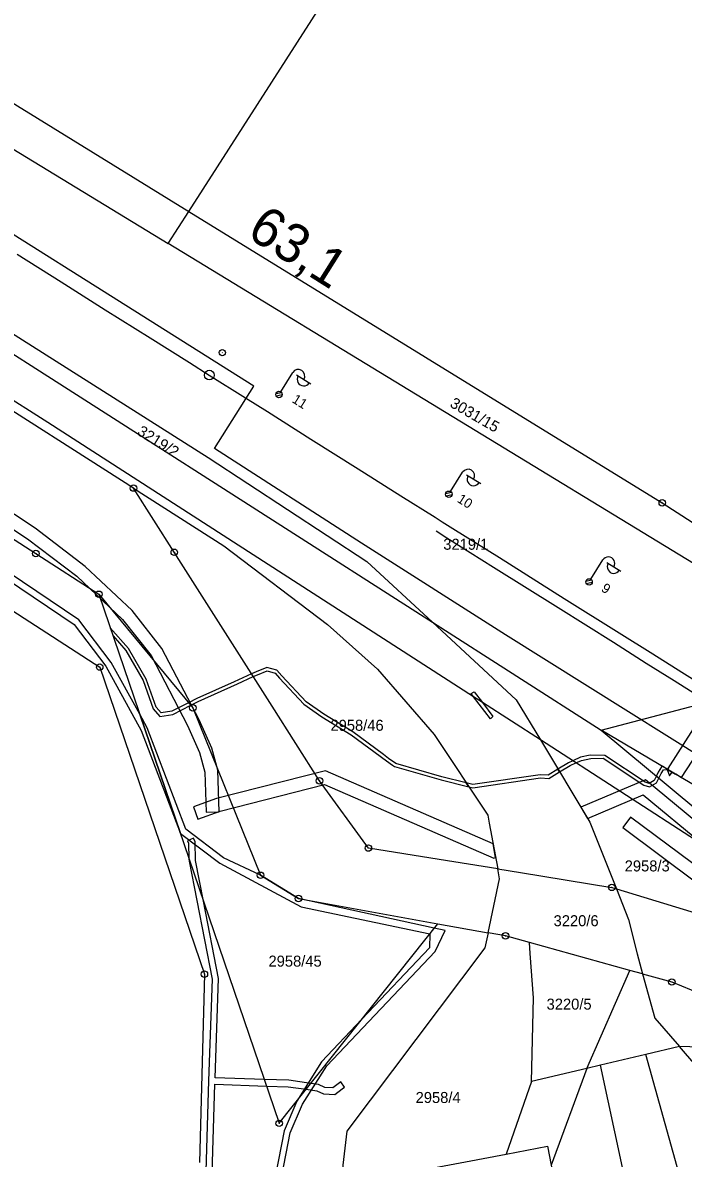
# Model space of a CAD drawing. Extents: x -621168 to -620292, y -1122748 to -1122069.
# Drawn here: x -620574.6 to -620472.5, y -1122640.4 to -1122465.1 of the extents above; entities that cross this region are included whole.
import ezdxf

# ---------------------------------------------------------------- set-up
doc = ezdxf.new("R2010")
doc.units = 0
for name, color, linetype in [('HranDP', 7, 'Continuous'), ('Hranice parcel', 7, 'Continuous'), ('Parcelní čísla', 7, 'Continuous'), ('Vnitřní kresba', 7, 'Continuous'), ('Vrstva 1', 7, 'Continuous'), ('Vrstva 14', 7, 'Continuous'), ('Vrstva 25', 7, 'Continuous'), ('Vrstva 7', 7, 'Continuous'), ('Věcná břemena k části', 7, 'Continuous'), ('Značky bodu BP', 7, 'Continuous')]:
    doc.layers.add(name, color=color, linetype=linetype)

msp = doc.modelspace()

# ---------------------------------------------------------------- linework, layer by layer
at = {"layer": 'HranDP'}
for p, q in [((-620445.8, -1122563.95), (-620552.09, -1122499.2)), ((-620511.29, -1122557.64), (-620485.21, -1122574.33))]:
    msp.add_line(p, q, dxfattribs=at)
for points in [[(-620847.72, -1122320.67), (-620838.83, -1122326.12), (-620768.63, -1122369.09), (-620748.53, -1122378.52), (-620702.13, -1122406.7), (-620691.02, -1122413.66), (-620638.48, -1122446.57), (-620552.09, -1122499.2)], [(-620821.12, -1122358.76), (-620741.46, -1122408.09), (-620679.51, -1122447.56), (-620545.92, -1122532.26), (-620521.41, -1122548.27), (-620511.29, -1122557.64)], [(-620378.58, -1122639.67), (-620411.71, -1122617.81), (-620485.21, -1122574.33)]]:
    msp.add_lwpolyline(points, dxfattribs=at)
at = {"layer": 'Hranice parcel'}
for p, q in [((-620548.9, -1122494.24), (-620477.85, -1122383.56)), ((-620688.16, -1122408.5), (-620548.9, -1122494.24)), ((-620552.09, -1122499.2), (-620548.9, -1122494.24)), ((-620548.9, -1122494.24), (-620475.79, -1122539.24)), ((-620445.8, -1122563.95), (-620552.09, -1122499.2)), ((-620511.29, -1122557.64), (-620485.21, -1122574.33)), ((-620482.88, -1122598.82), (-620481, -1122603.54)), ((-620510.44, -1122604.21), (-620502.69, -1122605.61)), ((-620546.5, -1122612), (-620547.23, -1122641.1)), ((-620478.83, -1122611.96), (-620476.96, -1122618.82)), ((-620476.96, -1122618.82), (-620473.14, -1122623.15)), ((-620473.14, -1122623.15), (-620478.32, -1122624.38)), ((-620478.32, -1122624.38), (-620485.31, -1122626.04))]:
    msp.add_line(p, q, dxfattribs=at)
for points in [[(-620847.72, -1122320.67), (-620838.83, -1122326.12), (-620768.63, -1122369.09), (-620748.53, -1122378.52), (-620702.13, -1122406.7), (-620691.02, -1122413.66), (-620638.48, -1122446.57), (-620552.09, -1122499.2)], [(-620821.12, -1122358.76), (-620741.46, -1122408.09), (-620679.51, -1122447.56), (-620545.92, -1122532.26), (-620521.41, -1122548.27), (-620511.29, -1122557.64)], [(-620821.12, -1122358.76), (-620807.67, -1122367.84), (-620645.72, -1122471.03), (-620587.17, -1122509.18), (-620511.29, -1122557.64)], [(-620557.45, -1122536.96), (-620684.91, -1122455.63), (-620825.92, -1122365.89)], [(-620501.2, -1122595.75), (-620510.22, -1122594.3), (-620521.17, -1122592.53), (-620528.72, -1122582.15), (-620536.04, -1122570.64), (-620547.19, -1122553.1), (-620551.15, -1122546.87), (-620557.45, -1122536.96)], [(-620557.45, -1122536.96), (-620543.5, -1122545.86), (-620527.5, -1122558.02), (-620519.77, -1122564.93), (-620511.02, -1122574.99), (-620502.74, -1122587.44), (-620502.51, -1122588.68), (-620501.2, -1122595.75)], [(-620475.79, -1122539.24), (-620450.17, -1122555.76), (-620441.78, -1122561.82)], [(-620576.58, -1122544.45), (-620572.54, -1122547.06), (-620562.8, -1122553.35)], [(-620581.67, -1122552.32), (-620562.67, -1122564.59), (-620546.5, -1122612)], [(-620562.8, -1122553.35), (-620548.28, -1122570.88), (-620537.83, -1122596.73), (-620531.96, -1122600.32), (-620510.44, -1122604.21)], [(-620562.8, -1122553.35), (-620534.95, -1122635.03), (-620510.44, -1122604.21)], [(-620511.29, -1122557.64), (-620498.35, -1122569.65), (-620494.61, -1122575.85)], [(-620485.21, -1122574.33), (-620466.94, -1122589.51), (-620387.14, -1122654.39)], [(-620378.58, -1122639.67), (-620411.71, -1122617.81), (-620485.21, -1122574.33)], [(-620494.61, -1122575.85), (-620486.95, -1122588.56), (-620482.88, -1122598.82)], [(-620450.13, -1122608.86), (-620469.8, -1122591.86), (-620494.61, -1122575.85)], [(-620502.69, -1122605.61), (-620500.92, -1122597.26), (-620501.2, -1122595.75)], [(-620501.2, -1122595.75), (-620497.68, -1122596.32), (-620483.58, -1122598.6), (-620482.88, -1122598.82)], [(-620482.88, -1122598.82), (-620472.56, -1122601.98), (-620450.13, -1122608.86)], [(-620481, -1122603.54), (-620479.67, -1122608.86), (-620478.83, -1122611.96)], [(-620502.69, -1122605.61), (-620503.19, -1122607.95), (-620524.52, -1122636.25), (-620525.13, -1122641.47), (-620525.33, -1122649.53), (-620522.29, -1122666.99)], [(-620496.31, -1122607.11), (-620500, -1122606.09), (-620502.69, -1122605.61)], [(-620485.31, -1122626.04), (-620487.46, -1122626.56), (-620495.96, -1122628.58), (-620495.65, -1122615.65), (-620496.18, -1122608.79), (-620496.31, -1122607.11)], [(-620478.83, -1122611.96), (-620480.79, -1122611.41), (-620496.31, -1122607.11)], [(-620478.83, -1122611.96), (-620474.31, -1122613.21), (-620471.33, -1122614.44), (-620452.73, -1122622.13)], [(-620450.04, -1122631.61), (-620461.53, -1122623.57), (-620463.51, -1122623.5), (-620473.14, -1122623.15)], [(-620410.99, -1122695.4), (-620434.88, -1122667.63), (-620473.14, -1122623.15)], [(-620438.61, -1122680.28), (-620439.78, -1122679.56), (-620451.85, -1122677.25), (-620463.28, -1122678.3), (-620478.32, -1122624.38)], [(-620486.3, -1122676.15), (-620484.21, -1122674.6), (-620475.28, -1122672.75), (-620485.31, -1122626.04)], [(-620522.29, -1122666.99), (-620515.05, -1122665.61), (-620511.55, -1122664.94), (-620512.68, -1122659.03), (-620515.78, -1122642.8), (-620506.17, -1122640.97), (-620499.9, -1122639.77), (-620493.5, -1122638.55), (-620492.94, -1122641.47), (-620486.3, -1122676.15)]]:
    msp.add_lwpolyline(points, dxfattribs=at)
at = {"layer": 'Vnitřní kresba'}
for p, q in [((-620570.69, -1122526.84), (-620613.12, -1122500)), ((-620504.94, -1122569.2), (-620570.69, -1122526.84)), ((-620485.21, -1122574.33), (-620445.8, -1122563.95)), ((-620505.32, -1122568.68), (-620504.84, -1122568.4)), ((-620504.94, -1122569.2), (-620505.32, -1122568.68)), ((-620503.56, -1122570.07), (-620504.94, -1122569.2)), ((-620502.33, -1122572.56), (-620504.94, -1122569.2)), ((-620504.84, -1122568.4), (-620503.56, -1122570.07)), ((-620494.61, -1122575.85), (-620503.56, -1122570.07)), ((-620503.56, -1122570.07), (-620501.96, -1122572.22)), ((-620501.96, -1122572.22), (-620502.33, -1122572.56)), ((-620487.46, -1122626.56), (-620480.79, -1122611.41)), ((-620487.46, -1122626.56), (-620492.94, -1122641.47)), ((-620495.96, -1122628.58), (-620499.9, -1122639.77))]:
    msp.add_line(p, q, dxfattribs=at)
at = {"layer": 'Vrstva 1'}
msp.add_line((-620544.95, -1122530.86), (-620538.89, -1122521.21), dxfattribs=at)
for points in [[(-620538.89, -1122521.21), (-620599.21, -1122483.22), (-620683.52, -1122429.44), (-620747.38, -1122389.13), (-620756.33, -1122383.52)], [(-620575.44, -1122500.82), (-620568.6, -1122505.12), (-620561.8, -1122509.42), (-620554.88, -1122513.77), (-620548.82, -1122517.58), (-620545.74, -1122519.52), (-620540.16, -1122523.03), (-620536.76, -1122525.16), (-620530.04, -1122529.4), (-620522.74, -1122534), (-620516.18, -1122538.13), (-620510.88, -1122541.46), (-620509.77, -1122542.15), (-620508.12, -1122543.19), (-620500.94, -1122547.69), (-620490.94, -1122553.98), (-620482.44, -1122559.31), (-620477.26, -1122562.56), (-620472.76, -1122565.38), (-620464.48, -1122570.59)], [(-620456.11, -1122587.12), (-620500.01, -1122559.59), (-620522.22, -1122545.45), (-620544.95, -1122530.86)]]:
    msp.add_lwpolyline(points, dxfattribs=at)
at = {"layer": 'Vrstva 14'}
msp.add_lwpolyline([(-620510.69, -1122543.55), (-620509.04, -1122544.63), (-620501.84, -1122549.15), (-620491.85, -1122555.41), (-620483.32, -1122560.77), (-620478.25, -1122563.97), (-620473.97, -1122566.66), (-620465.4, -1122572.05), (-620457.72, -1122576.88), (-620450.01, -1122581.72), (-620442.29, -1122586.56), (-620434.63, -1122591.38), (-620426.95, -1122596.21), (-620419.24, -1122601.09), (-620411.54, -1122605.96), (-620403.8, -1122610.84), (-620395.25, -1122616.25), (-620387.51, -1122621.12), (-620379.87, -1122625.94), (-620375.57, -1122628.64), (-620373.08, -1122630.21)], dxfattribs=at)
at = {"layer": 'Vrstva 25'}
for p, q in [((-620534.71, -1122522.08), (-620532.84, -1122519.12)), ((-620532.25, -1122519.49), (-620530.05, -1122520.88)), ((-620535.46, -1122522.37), (-620534.6, -1122522.18)), ((-620535.41, -1122522.74), (-620534.48, -1122522.53)), ((-620508.48, -1122537.48), (-620506.62, -1122534.52)), ((-620506.02, -1122534.89), (-620503.82, -1122536.27)), ((-620509.23, -1122537.78), (-620508.37, -1122537.58)), ((-620509.18, -1122538.15), (-620508.25, -1122537.94)), ((-620486.83, -1122551.02), (-620484.96, -1122548.06)), ((-620484.37, -1122548.43), (-620482.17, -1122549.81)), ((-620487.57, -1122551.32), (-620486.72, -1122551.12)), ((-620487.53, -1122551.69), (-620486.59, -1122551.48))]:
    msp.add_line(p, q, dxfattribs=at)
for centre in [(-620534.98, -1122522.5), (-620508.74, -1122537.91), (-620487.09, -1122551.45)]:
    msp.add_circle(centre, 0.5, dxfattribs=at)
for centre, start, end in [((-620532, -1122519.65), 327.7645, 147.7645), ((-620531.16, -1122520.19), 147.0619, 328.467), ((-620505.77, -1122535.05), 327.8645, 147.8645), ((-620504.93, -1122535.59), 147.162, 328.5671), ((-620484.12, -1122548.59), 327.8803, 147.8803), ((-620483.28, -1122549.13), 147.1777, 328.5829)]:
    msp.add_arc(centre, 1, start, end, dxfattribs=at)
at = {"layer": 'Vrstva 7'}
msp.add_line((-620543.78, -1122516.02), (-620543.69, -1122516.08), dxfattribs=at)
for centre, radius in [((-620543.73, -1122516.05), 0.5), ((-620545.74, -1122519.52), 0.75)]:
    msp.add_circle(centre, radius, dxfattribs=at)
at = {"layer": 'Věcná břemena k části'}
for points in [[(-620662.49, -1122492.8), (-620663.99, -1122495.13), (-620660.86, -1122494.48), (-620566.61, -1122558.04), (-620561.72, -1122564.46), (-620556.24, -1122574.37), (-620550.21, -1122590.27), (-620556.49, -1122571.86), (-620560.88, -1122563.9), (-620565.91, -1122557.3), (-620661.78, -1122492.65)], [(-620456.96, -1122557.15), (-620459.28, -1122555.74), (-620474.94, -1122580.24), (-620474.78, -1122580.35), (-620474.85, -1122580.46), (-620473.73, -1122581.12), (-620473.69, -1122581.06), (-620472.83, -1122581.63), (-620471.16, -1122579.11), (-620461.86, -1122564.94)], [(-620551.52, -1122571.42), (-620553.2, -1122571.67), (-620553.96, -1122570.77), (-620555.49, -1122566.47), (-620558.24, -1122561.71), (-620561.03, -1122558.53), (-620560.61, -1122559.77), (-620558.64, -1122562.01), (-620555.95, -1122566.69), (-620554.4, -1122571.03), (-620553.4, -1122572.21), (-620551.36, -1122571.9), (-620548.6, -1122570.49), (-620547.46, -1122569.91), (-620541.41, -1122567.17), (-620538.95, -1122566.06), (-620538.32, -1122565.78), (-620536.81, -1122565.17), (-620535.58, -1122565.51), (-620534.89, -1122566.28), (-620531.14, -1122570.32), (-620528.34, -1122572.29), (-620523.83, -1122575.03), (-620518.35, -1122579.09), (-620517.46, -1122579.72), (-620517.13, -1122579.95), (-620509.95, -1122582.01), (-620505.65, -1122583.07), (-620506.06, -1122582.46), (-620509.83, -1122581.53), (-620516.91, -1122579.49), (-620518.05, -1122578.69), (-620518.83, -1122578.11), (-620523.55, -1122574.61), (-620528.06, -1122571.87), (-620530.8, -1122569.94), (-620534.53, -1122565.94), (-620535.3, -1122565.07), (-620536.85, -1122564.65), (-620538.52, -1122565.32), (-620539.22, -1122565.64), (-620541.91, -1122566.85), (-620547.68, -1122569.45), (-620548.93, -1122570.09)], [(-620476.66, -1122582.45), (-620476.31, -1122581.73), (-620476.7, -1122581.4), (-620477.04, -1122582.09), (-620477.83, -1122582.55), (-620478.41, -1122582.37), (-620484.64, -1122578.24), (-620486.9, -1122578.2), (-620488.41, -1122578.51), (-620489.62, -1122579.07), (-620490.27, -1122579.37), (-620491.9, -1122580.35), (-620491.64, -1122580.78), (-620490.03, -1122579.81), (-620489.12, -1122579.39), (-620488.25, -1122578.99), (-620486.8, -1122578.7), (-620484.92, -1122578.66), (-620478.63, -1122582.83), (-620477.77, -1122583.09)], [(-620476.7, -1122581.4), (-620476.31, -1122581.73), (-620475.97, -1122581.04), (-620475.6, -1122580.46), (-620475.01, -1122580.41), (-620474.65, -1122581.39), (-620474.27, -1122580.8), (-620474.85, -1122580.46), (-620475.69, -1122579.96), (-620475.88, -1122579.98), (-620476.41, -1122580.8)], [(-620547.49, -1122588.06), (-620544.04, -1122586.82), (-620527.96, -1122582.73), (-620501.79, -1122594.1), (-620501.53, -1122593.99), (-620501.92, -1122591.86), (-620527.8, -1122580.63), (-620544.62, -1122584.9), (-620548.17, -1122586.18)], [(-620505.65, -1122583.07), (-620505.06, -1122583.21), (-620494.61, -1122581.71), (-620493.3, -1122581.78), (-620491.64, -1122580.78), (-620491.9, -1122580.35), (-620493.42, -1122581.28), (-620494.63, -1122581.21), (-620505.04, -1122582.71), (-620506.06, -1122582.46)], [(-620481.88, -1122589.35), (-620470.44, -1122597.88), (-620469.24, -1122596.28), (-620480.68, -1122587.75)]]:
    msp.add_lwpolyline(points, close=True, dxfattribs=at)
for points in [[(-620586.86, -1122536.18), (-620573.8, -1122544.78), (-620566.2, -1122550.57), (-620559.13, -1122557.24), (-620554.74, -1122562.8), (-620549.11, -1122573.63), (-620547.24, -1122577.78), (-620546.44, -1122580.81), (-620546.21, -1122587), (-620544.21, -1122586.92), (-620544.44, -1122580.51), (-620545.34, -1122577.1), (-620547.31, -1122572.75), (-620553.06, -1122561.7), (-620557.65, -1122555.88), (-620564.9, -1122549.05), (-620572.64, -1122543.14), (-620585.76, -1122534.5)], [(-620534.53, -1122643.11), (-620533.24, -1122636.48), (-620531.35, -1122632.09), (-620527.61, -1122626.14), (-620510.87, -1122608.51), (-620509.33, -1122605.27), (-620511, -1122604.91), (-620531.96, -1122600.32), (-620537.83, -1122596.73), (-620543.57, -1122594.05), (-620549.38, -1122589.64), (-620555.33, -1122573.96), (-620556.49, -1122571.86), (-620550.21, -1122590.27), (-620544.11, -1122594.89), (-620531.56, -1122601.62), (-620511.69, -1122605.79), (-620511.71, -1122607.93), (-620522.17, -1122618.96), (-620528.4, -1122625.53), (-620532.24, -1122631.63), (-620534.2, -1122636.18), (-620535.53, -1122643.03)], [(-620394.32, -1122666.74), (-620417.42, -1122647.16), (-620431.52, -1122639.64), (-620457.44, -1122620.38), (-620448.45, -1122606.75), (-620478.4, -1122581.98), (-620488.36, -1122586.21), (-620487.32, -1122587.95), (-620478.74, -1122584.3), (-620451.11, -1122607.15), (-620460.16, -1122620.86), (-620432.6, -1122641.34), (-620418.54, -1122648.82), (-620395.34, -1122668.49)], [(-620545.91, -1122663.42), (-620544.9, -1122629), (-620536.91, -1122629.27), (-620533.56, -1122629.38), (-620530.78, -1122629.78), (-620529.16, -1122630.02), (-620528.1, -1122630.5), (-620526.34, -1122630.56), (-620525.24, -1122629.73), (-620524.84, -1122629.43), (-620525.44, -1122628.63), (-620525.84, -1122628.93), (-620526.66, -1122629.54), (-620527.88, -1122629.5), (-620528.88, -1122629.06), (-620530.06, -1122628.89), (-620533.48, -1122628.38), (-620537.26, -1122628.25), (-620544.86, -1122628), (-620544.3, -1122612.69), (-620546.64, -1122600.75), (-620547.87, -1122594.46), (-620547.94, -1122591.57), (-620548.19, -1122591), (-620549.11, -1122591.4), (-620548.94, -1122591.79), (-620548.88, -1122594.18), (-620548.87, -1122594.56), (-620545.3, -1122612.77), (-620545.88, -1122628.46), (-620546.91, -1122663.38)]]:
    msp.add_lwpolyline(points, dxfattribs=at)
at = {"layer": 'Značky bodu BP'}
for centre, radius in [((-620557.45, -1122536.96), 0.5), ((-620557.45, -1122536.96), 0.0303), ((-620475.79, -1122539.24), 0.5), ((-620475.79, -1122539.24), 0.0303), ((-620572.54, -1122547.06), 0.5), ((-620551.15, -1122546.87), 0.5), ((-620572.54, -1122547.06), 0.0303), ((-620551.15, -1122546.87), 0.0303), ((-620562.8, -1122553.35), 0.5), ((-620562.8, -1122553.35), 0.0303), ((-620562.67, -1122564.59), 0.5), ((-620562.67, -1122564.59), 0.0303), ((-620548.28, -1122570.88), 0.5), ((-620548.28, -1122570.88), 0.0303), ((-620528.72, -1122582.15), 0.5), ((-620528.72, -1122582.15), 0.0303), ((-620521.17, -1122592.53), 0.5), ((-620521.17, -1122592.53), 0.0303), ((-620537.83, -1122596.73), 0.5), ((-620537.83, -1122596.73), 0.0303), ((-620483.58, -1122598.6), 0.5), ((-620483.58, -1122598.6), 0.0303), ((-620531.96, -1122600.32), 0.5), ((-620531.96, -1122600.32), 0.0303), ((-620500, -1122606.09), 0.5), ((-620500, -1122606.09), 0.0303), ((-620546.5, -1122612), 0.5), ((-620546.5, -1122612), 0.0303), ((-620474.31, -1122613.21), 0.5), ((-620474.31, -1122613.21), 0.0303), ((-620534.95, -1122635.03), 0.5), ((-620534.95, -1122635.03), 0.0303)]:
    msp.add_circle(centre, radius, dxfattribs=at)

# ---------------------------------------------------------------- texts
at = {"layer": 'Parcelní čísla'}
for s, rotation, p in [('3031/15', 330, (-620508.71, -1122524.33)), ('3219/2', 328, (-620557.01, -1122528.62))]:
    msp.add_text(s, height=1.7, rotation=rotation, dxfattribs=at).set_placement(p)
for s, p in [('3219/1', (-620509.61, -1122546.48)), ('2958/46', (-620527.03, -1122574.43)), ('2958/3', (-620481.59, -1122596.14)), ('3220/6', (-620492.57, -1122604.6)), ('2958/45', (-620536.6, -1122610.84)), ('3220/5', (-620493.65, -1122617.48)), ('2958/4', (-620513.88, -1122631.89))]:
    msp.add_text(s, height=1.7, dxfattribs=at).set_placement(p)
at = {"layer": 'Vrstva 25'}
for s, rotation, p in [('11', 327.7645, (-620533.09, -1122523.63)), ('10', 327.8645, (-620507.58, -1122539.02)), ('9', 327.8803, (-620485.33, -1122552.79))]:
    msp.add_text(s, height=1.5, rotation=rotation, dxfattribs=at).set_placement(p)
at = {"layer": 'Vrstva 7'}
msp.add_text('63,1', height=6, rotation=327.8195, dxfattribs=at).set_placement((-620540.16, -1122498.07))

doc.saveas('drawing.dxf')
